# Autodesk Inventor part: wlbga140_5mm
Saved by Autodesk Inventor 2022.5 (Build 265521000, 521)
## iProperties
Created: 2024-12
Part Number: wlbga140_5mm
Material: Generic
Document SubType Name: Modeling
Designer: AdminForWorker
Density: 1 g/cm^3
Appearance: Default
Title: wlbga140_5mm v1
Author: AdminForWorker
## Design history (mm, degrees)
feature "Body1"
feature "Body64"
feature "Body112"
feature "Body113"
feature "Body114"
feature "Body115"
feature "Body116"
feature "Body117"
feature "Body118"
feature "Body119"
feature "Body120"
feature "Body121"
feature "Body122"
feature "Body123"
feature "Body124"
feature "Body125"
feature "Body126"
feature "Body127"
feature "Body128"
feature "Body129"
feature "Body130"
feature "Body131"
feature "Body132"
feature "Body133"
feature "Body134"
feature "Body135"
feature "Body136"
feature "Body137"
feature "Body138"
feature "Body139"
feature "Body140"
feature "Body141"
feature "Body142"
feature "Body143"
feature "Body144"
feature "Body145"
feature "Body146"
feature "Body147"
feature "Body148"
feature "Body149"
feature "Body150"
feature "Body151"
feature "Body152"
feature "Body153"
feature "Body154"
feature "Body155"
feature "Body156"
feature "Body157"
feature "Body158"
feature "Body159"
feature "Body160"
feature "Body161"
feature "Body162"
feature "Body163"
feature "Body164"
feature "Body165"
feature "Body166"
feature "Body167"
feature "Body168"
feature "Body169"
feature "Body170"
feature "Body171"
feature "Body172"
feature "Body173"
feature "Body174"
feature "Body175"
feature "Body176"
feature "Body177"
feature "Body178"
feature "Body179"
feature "Body180"
feature "Body181"
feature "Body182"
feature "Body183"
feature "Body184"
feature "Body185"
feature "Body186"
feature "Body187"
feature "Body188"
feature "Body189"
feature "Body190"
feature "Body191"
feature "Body192"
feature "Body193"
feature "Body194"
feature "Body195"
feature "Body196"
feature "Body197"
feature "Body198"
feature "Body199"
feature "Body200"
feature "Body201"
feature "Body202"
feature "Body203"
feature "Body204"
feature "Body205"
feature "Body206"
feature "Body207"
feature "Body208"
feature "Body209"
feature "Body210"
feature "Body211"
feature "Body212"
feature "Body213"
feature "Body214"
feature "Body215"
feature "Body216"
feature "Body217"
feature "Body218"
feature "Body219"
feature "Body220"
feature "Body221"
feature "Body222"
feature "Body223"
feature "Body224"
feature "Body225"
feature "Body226"
feature "Body227"
feature "Body228"
feature "Body229"
feature "Body230"
feature "Body231"
feature "Body232"
feature "Body233"
feature "Body234"
feature "Body235"
feature "Body236"
feature "Body237"
feature "Body238"
feature "Body239"
feature "Body240"
feature "Body241"
feature "Body242"
feature "Body243"
feature "Body244"
feature "Body245"
feature "Body246"
feature "Body247"
feature "Body248"
feature "Body249"
feature "Body250"
body "Solid1"
body "Solid2"
body "Solid3"
body "Solid4"
body "Solid5"
body "Solid6"
body "Solid7"
body "Solid8"
body "Solid9"
body "Solid10"
body "Solid11"
body "Solid12"
body "Solid13"
body "Solid14"
body "Solid15"
body "Solid16"
body "Solid17"
body "Solid18"
body "Solid19"
body "Solid20"
body "Solid21"
body "Solid22"
body "Solid23"
body "Solid24"
body "Solid25"
body "Solid26"
body "Solid27"
body "Solid28"
body "Solid29"
body "Solid30"
body "Solid31"
body "Solid32"
body "Solid33"
body "Solid34"
body "Solid35"
body "Solid36"
body "Solid37"
body "Solid38"
body "Solid39"
body "Solid40"
body "Solid41"
body "Solid42"
body "Solid43"
body "Solid44"
body "Solid45"
body "Solid46"
body "Solid47"
body "Solid48"
body "Solid49"
body "Solid50"
body "Solid51"
body "Solid52"
body "Solid53"
body "Solid54"
body "Solid55"
body "Solid56"
body "Solid57"
body "Solid58"
body "Solid59"
body "Solid60"
body "Solid61"
body "Solid62"
body "Solid63"
body "Solid64"
body "Solid65"
body "Solid66"
body "Solid67"
body "Solid68"
body "Solid69"
body "Solid70"
body "Solid71"
body "Solid72"
body "Solid73"
body "Solid74"
body "Solid75"
body "Solid76"
body "Solid77"
body "Solid78"
body "Solid79"
body "Solid80"
body "Solid81"
body "Solid82"
body "Solid83"
body "Solid84"
body "Solid85"
body "Solid86"
body "Solid87"
body "Solid88"
body "Solid89"
body "Solid90"
body "Solid91"
body "Solid92"
body "Solid93"
body "Solid94"
body "Solid95"
body "Solid96"
body "Solid97"
body "Solid98"
body "Solid99"
body "Solid100"
body "Solid101"
body "Solid102"
body "Solid103"
body "Solid104"
body "Solid105"
body "Solid106"
body "Solid107"
body "Solid108"
body "Solid109"
body "Solid110"
body "Solid111"
body "Solid112"
body "Solid113"
body "Solid114"
body "Solid115"
body "Solid116"
body "Solid117"
body "Solid118"
body "Solid119"
body "Solid120"
body "Solid121"
body "Solid122"
body "Solid123"
body "Solid124"
body "Solid125"
body "Solid126"
body "Solid127"
body "Solid128"
body "Solid129"
body "Solid130"
body "Solid131"
body "Solid132"
body "Solid133"
body "Solid134"
body "Solid135"
body "Solid136"
body "Solid137"
body "Solid138"
body "Solid139"
body "Solid140"
body "Solid141"
